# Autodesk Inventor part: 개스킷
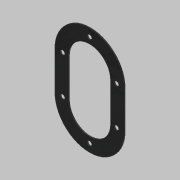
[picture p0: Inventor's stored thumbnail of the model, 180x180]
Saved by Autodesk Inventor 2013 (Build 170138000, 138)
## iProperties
Created: 2019-03
Part Number: 개스킷
Material: 고무
Document SubType Name: Modeling
Designer: mduedu
Density: 1 g/cm^3
Author: mduedu
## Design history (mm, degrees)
sketch "스케치1"
  geometry: L1 (-62, 40)-(62, 40); L2 (62, 40)-(62, -40); L3 (62, -40)-(-62, -40); L4 (-62, -40)-(-62, 40); L5 (-62, 40)-(62, -40); L6 (62, 40)-(-62, -40); 1 further point
  constraints: 12 end point, 2 midpoint, 2 parallel, 1 horizontal, 1 perpendicular
  dimensions: "d21" = 124 distance of L2.end L3.end; "d22" = 80 distance of L1.end L2.end
extrude "돌출1" new body sketch "스케치1" distance "d3" = 1; taper "d4" = 0 deg
fillet "모깎기2"
fillet "모깎기3"
sketch "스케치2" dims "d6" = 48
  geometry: L1 (-24, -22)-(24, -22); L2 (24, -22)-(24, 22); L3 (24, 22)-(-24, 22); L4 (-24, 22)-(-24, -22); L5 (-24, -22)-(24, 22); L6 (24, -22)-(-24, 22); 3 further points
  constraints: 12 end point, 4 midpoint, 2 horizontal alignment, 2 parallel, 1 horizontal, 1 perpendicular, 4 other
  dimensions: "d8" = 22 distance from line of L3 point (0, 0)
extrude "돌출2" cut sketch "스케치2" stored distance "d9" = 1; taper "d10" = 0 deg
sketch "스케치3"
  geometry: L1 (24, -22)-(24, 22) reference; L2 (-24, 22)-(-24, -22) reference; L3 (31, 22)-(31, -22); L4 (-31, -22)-(-31, 22); A1 r 24 centre (0, 22) between (24, 22) and (-24, 22) reference; A2 r 24 centre (0, -22) between (-24, -22) and (24, -22) reference; A3 r 31 centre (0, 22) between (31, 22) and (-31, 22); A4 r 31 centre (0, -22) between (-31, -22) and (31, -22); 7 further points
  constraints: 6 point on circle, 4 coincident, 4 end point, 2 centre point, 3 other
  dimensions: "d26" = 62 distance between parallel lines of L3 L4; "d28" = 7 distance between parallel lines of L4 L2 (derived); "d29" = 48 distance between parallel lines of L1 L2 (derived); "d30" = 31 radius of A3 (derived)
hole "구멍1" sketch "스케치3" at (0, 53), (31, 22), (31, -22), (0, -53), (-31, -22), (-31, 22) diameter "d14" = 5; stored, may be unused: countersink angle "d18" = 90 deg, drill point angle "d20" = 118 deg; dims "d15" = 6, "d16" = 4, "d17" = 2, "d19" = 8
node "솔리드1"
